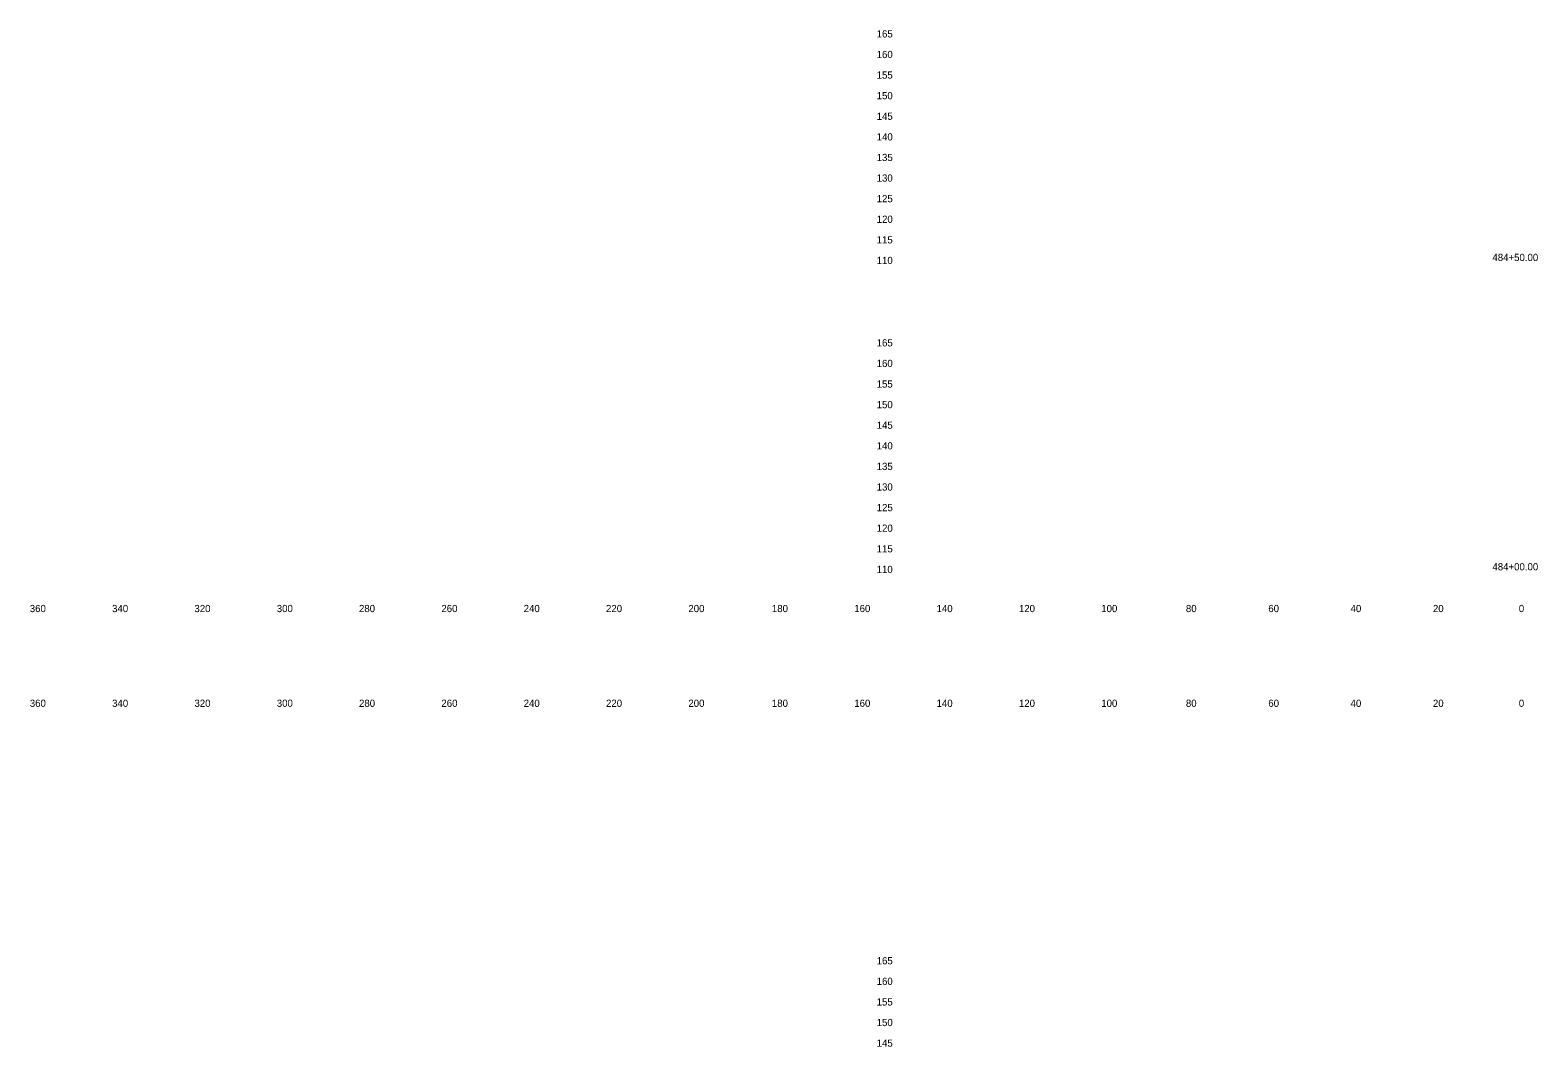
# Model space of a CAD drawing. Extents: x 21281 to 22024, y 6472 to 15198.
# Drawn here: x 21280.5 to 21646.7, y 13269.8 to 13516.6 of the extents above; entities that cross this region are included whole.
import ezdxf

# ---------------------------------------------------------------- set-up
doc = ezdxf.new("R2010")
doc.units = 0
for name, color, linetype in [('Draft_XS_Grid', 7, 'Continuous'), ('Draft_XS_Text', 7, 'Continuous'), ('SLOPE_STAKES_FILL', 7, 'Continuous')]:
    doc.layers.add(name, color=color, linetype=linetype)

msp = doc.modelspace()

# ---------------------------------------------------------------- texts
at = {"layer": 'Draft_XS_Grid'}
for s, p in [('  165  ', (21484.84, 13514.84)), ('  160  ', (21484.84, 13509.84)), ('  155  ', (21484.84, 13504.84)), ('  150  ', (21484.84, 13499.84)), ('  145  ', (21484.84, 13494.84)), ('  140  ', (21484.84, 13489.84)), ('  135  ', (21484.84, 13484.84)), ('  130  ', (21484.84, 13479.84)), ('  125  ', (21484.84, 13474.84)), ('  120  ', (21484.84, 13469.84)), ('  115  ', (21484.84, 13464.84)), ('  110  ', (21484.84, 13459.84)), ('  165  ', (21484.84, 13439.84)), ('  160  ', (21484.84, 13434.84)), ('  155  ', (21484.84, 13429.84)), ('  150  ', (21484.84, 13424.84)), ('  145  ', (21484.84, 13419.84)), ('  140  ', (21484.84, 13414.84)), ('  135  ', (21484.84, 13409.84)), ('  130  ', (21484.84, 13404.84)), ('  125  ', (21484.84, 13399.84)), ('  120  ', (21484.84, 13394.84)), ('  115  ', (21484.84, 13389.84)), ('  110  ', (21484.84, 13384.84)), ('  165  ', (21484.84, 13289.84)), ('  160  ', (21484.84, 13284.84)), ('  155  ', (21484.84, 13279.84)), ('  150  ', (21484.84, 13274.84)), ('  145  ', (21484.84, 13269.84))]:
    msp.add_text(s, height=1.75, dxfattribs=at).set_placement(p)
at = {"layer": 'Draft_XS_Text'}
for s, p in [('  360  ', (21279.14, 13375.34)), ('  340  ', (21299.13, 13375.34)), ('  320  ', (21319.13, 13375.34)), ('  300  ', (21339.13, 13375.34)), ('  280  ', (21359.1, 13375.34)), ('  260  ', (21379.11, 13375.34)), ('  240  ', (21399.1, 13375.34)), ('  220  ', (21419.1, 13375.34)), ('  200  ', (21439.1, 13375.34)), ('  180  ', (21459.39, 13375.34)), ('  160  ', (21479.4, 13375.34)), ('  140  ', (21499.39, 13375.34)), ('  120  ', (21519.39, 13375.34)), ('  100  ', (21539.39, 13375.34)), ('  80  ', (21559.95, 13375.34)), ('  60  ', (21579.97, 13375.34)), ('  40  ', (21599.95, 13375.34)), ('  20  ', (21619.95, 13375.34)), ('  0  ', (21640.81, 13375.34)), ('  0  ', (21640.81, 13375.34)), ('  360  ', (21279.14, 13352.34)), ('  340  ', (21299.13, 13352.34)), ('  320  ', (21319.13, 13352.34)), ('  300  ', (21339.13, 13352.34)), ('  280  ', (21359.1, 13352.34)), ('  260  ', (21379.11, 13352.34)), ('  240  ', (21399.1, 13352.34)), ('  220  ', (21419.1, 13352.34)), ('  200  ', (21439.1, 13352.34)), ('  180  ', (21459.39, 13352.34)), ('  160  ', (21479.4, 13352.34)), ('  140  ', (21499.39, 13352.34)), ('  120  ', (21519.39, 13352.34)), ('  100  ', (21539.39, 13352.34)), ('  80  ', (21559.95, 13352.34)), ('  60  ', (21579.97, 13352.34)), ('  40  ', (21599.95, 13352.34)), ('  20  ', (21619.95, 13352.34)), ('  0  ', (21640.81, 13352.34)), ('  0  ', (21640.81, 13352.34))]:
    msp.add_text(s, height=1.75, dxfattribs=at).set_placement(p)
at = {"layer": 'SLOPE_STAKES_FILL'}
for s, p in [('  484+50.00  ', (21634.4, 13460.57)), ('  484+00.00  ', (21634.4, 13385.49))]:
    msp.add_text(s, height=1.75, dxfattribs=at).set_placement(p)

doc.saveas('drawing.dxf')
